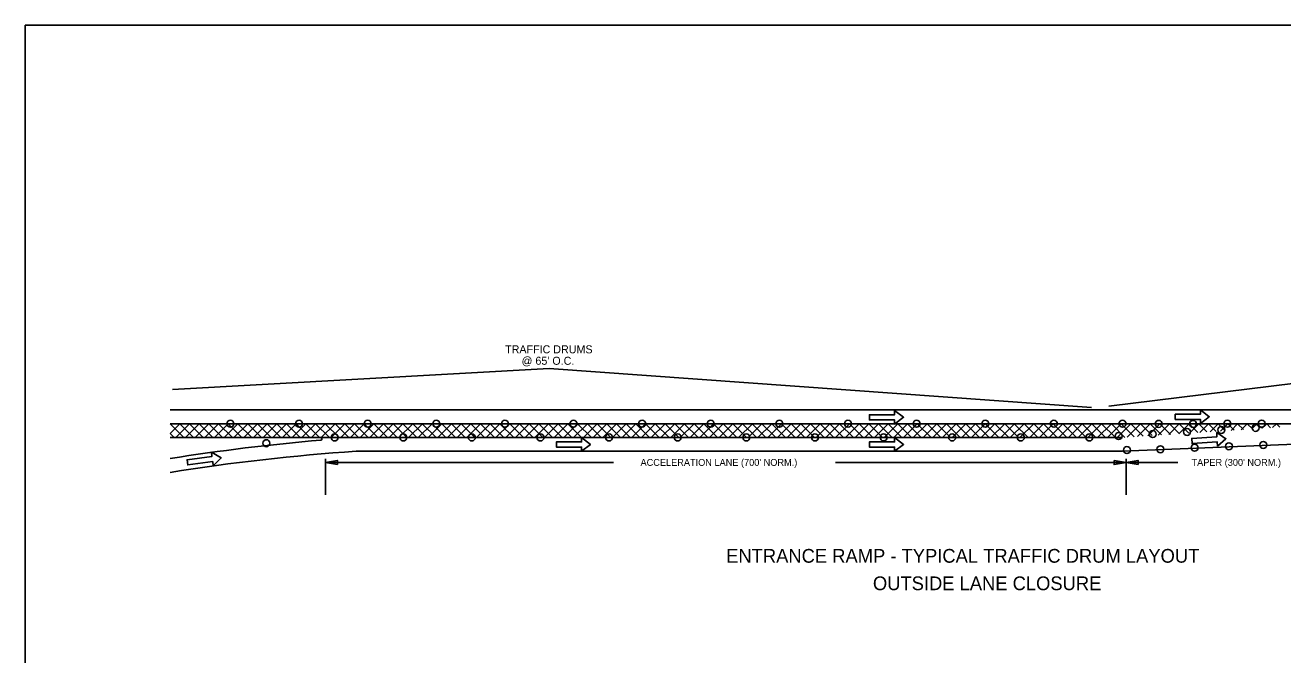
# Model space of a CAD drawing. Extents: x 1374027 to 1374537, y 380415 to 381405.
# Drawn here: x 1374367.1 to 1374477.1, y 380690.2 to 380745.2 of the extents above; entities that cross this region are included whole.
import ezdxf

# ---------------------------------------------------------------- set-up
doc = ezdxf.new("R2010")
doc.units = 0
for name, color, linetype in [('Default', 7, 'Continuous'), ('DSN_DRFT_Junk-No-Plot', 7, 'Continuous'), ('Edge of Lanes', 7, 'Continuous'), ('Level 1', 7, 'Continuous'), ('Level 40', 7, 'Continuous'), ('NOTES', 7, 'Continuous')]:
    doc.layers.add(name, color=color, linetype=linetype)

msp = doc.modelspace()

# ---------------------------------------------------------------- linework, layer by layer
at = {"layer": 'Default'}
for points in [[(1374469.84, 380710.37), (1374470.62, 380710.97), (1374469.84, 380711.57), (1374469.84, 380711.19), (1374467.64, 380711.19), (1374467.64, 380710.74), (1374469.84, 380710.74)], [(1374443.11, 380710.32), (1374443.89, 380710.92), (1374443.11, 380711.52), (1374443.11, 380711.15), (1374440.9, 380711.15), (1374440.9, 380710.7), (1374443.11, 380710.7)], [(1374471.35, 380708.4), (1374472.08, 380709.05), (1374471.27, 380709.59), (1374471.29, 380709.22), (1374469.09, 380709.07), (1374469.12, 380708.62), (1374471.32, 380708.77)], [(1374415.73, 380707.95), (1374416.51, 380708.55), (1374415.73, 380709.15), (1374415.73, 380708.77), (1374413.53, 380708.77), (1374413.53, 380708.32), (1374415.73, 380708.32)], [(1374443.11, 380707.95), (1374443.89, 380708.55), (1374443.11, 380709.15), (1374443.11, 380708.77), (1374440.9, 380708.77), (1374440.9, 380708.32), (1374443.11, 380708.32)], [(1374383.53, 380706.68), (1374384.23, 380707.38), (1374383.38, 380707.87), (1374383.42, 380707.5), (1374381.24, 380707.21), (1374381.3, 380706.76), (1374383.48, 380707.05)]]:
    msp.add_lwpolyline(points, close=True, dxfattribs=at)
at = {"layer": 'DSN_DRFT_Junk-No-Plot'}
for points in [[(1374367.08, 380745.17), (1374537.08, 380745.17), (1374537.08, 380635.17), (1374367.08, 380635.17)], [(1374367.08, 380745.17), (1374367.08, 380635.17), (1374537.08, 380635.17), (1374537.08, 380745.17)]]:
    msp.add_lwpolyline(points, close=True, dxfattribs=at)
at = {"layer": 'Edge of Lanes'}
for p, q in [((1374519.71, 380711.56), (1374379.75, 380711.56)), ((1374519.71, 380710.36), (1374379.75, 380710.36)), ((1374379.75, 380709.51), (1374380.6, 380710.36)), ((1374379.75, 380710.36), (1374379.75, 380710.36)), ((1374379.75, 380710.36), (1374380.95, 380709.16)), ((1374379.75, 380709.51), (1374380.1, 380709.16)), ((1374380.25, 380709.16), (1374381.45, 380710.36)), ((1374380.6, 380710.36), (1374381.8, 380709.16)), ((1374381.1, 380709.16), (1374382.3, 380710.36)), ((1374381.45, 380710.36), (1374382.65, 380709.16)), ((1374381.95, 380709.16), (1374383.15, 380710.36)), ((1374382.3, 380710.36), (1374383.5, 380709.16)), ((1374382.8, 380709.16), (1374384, 380710.36)), ((1374383.15, 380710.36), (1374384.35, 380709.16)), ((1374383.64, 380709.16), (1374384.84, 380710.36)), ((1374384, 380710.36), (1374385.2, 380709.16)), ((1374384.49, 380709.16), (1374385.69, 380710.36)), ((1374384.84, 380710.36), (1374386.04, 380709.16)), ((1374385.34, 380709.16), (1374386.54, 380710.36)), ((1374385.69, 380710.36), (1374386.89, 380709.16)), ((1374386.19, 380709.16), (1374387.39, 380710.36)), ((1374386.54, 380710.36), (1374387.74, 380709.16)), ((1374387.04, 380709.16), (1374388.24, 380710.36)), ((1374387.39, 380710.36), (1374388.59, 380709.16)), ((1374387.89, 380709.16), (1374389.09, 380710.36)), ((1374388.24, 380710.36), (1374389.44, 380709.16)), ((1374388.74, 380709.16), (1374389.94, 380710.36)), ((1374389.09, 380710.36), (1374390.29, 380709.16)), ((1374389.58, 380709.16), (1374390.78, 380710.36)), ((1374389.94, 380710.36), (1374391.14, 380709.16)), ((1374390.43, 380709.16), (1374391.63, 380710.36)), ((1374390.78, 380710.36), (1374391.98, 380709.16)), ((1374391.28, 380709.16), (1374392.48, 380710.36)), ((1374391.63, 380710.36), (1374392.83, 380709.16)), ((1374392.13, 380709.16), (1374393.33, 380710.36)), ((1374392.48, 380710.36), (1374393.68, 380709.16)), ((1374392.98, 380709.16), (1374394.18, 380710.36)), ((1374393.33, 380710.36), (1374394.53, 380709.16)), ((1374393.83, 380709.16), (1374395.03, 380710.36)), ((1374394.18, 380710.36), (1374395.38, 380709.16)), ((1374394.68, 380709.16), (1374395.88, 380710.36)), ((1374395.03, 380710.36), (1374396.23, 380709.16)), ((1374395.52, 380709.16), (1374396.72, 380710.36)), ((1374395.87, 380710.36), (1374397.08, 380709.16)), ((1374396.37, 380709.16), (1374397.57, 380710.36)), ((1374396.72, 380710.36), (1374397.92, 380709.16)), ((1374397.22, 380709.16), (1374398.42, 380710.36)), ((1374397.57, 380710.36), (1374398.77, 380709.16)), ((1374398.07, 380709.16), (1374399.27, 380710.36)), ((1374398.42, 380710.36), (1374399.62, 380709.16)), ((1374398.92, 380709.16), (1374400.12, 380710.36)), ((1374399.27, 380710.36), (1374400.47, 380709.16)), ((1374399.77, 380709.16), (1374400.97, 380710.36)), ((1374400.12, 380710.36), (1374401.32, 380709.16)), ((1374400.61, 380709.16), (1374401.82, 380710.36)), ((1374400.97, 380710.36), (1374402.17, 380709.16)), ((1374401.46, 380709.16), (1374402.66, 380710.36)), ((1374401.81, 380710.36), (1374403.01, 380709.16)), ((1374402.31, 380709.16), (1374403.51, 380710.36)), ((1374402.66, 380710.36), (1374403.86, 380709.16)), ((1374403.16, 380709.16), (1374404.36, 380710.36)), ((1374403.51, 380710.36), (1374404.71, 380709.16)), ((1374404.01, 380709.16), (1374405.21, 380710.36)), ((1374404.36, 380710.36), (1374405.56, 380709.16)), ((1374404.86, 380709.16), (1374406.06, 380710.36)), ((1374405.21, 380710.36), (1374406.41, 380709.16)), ((1374405.71, 380709.16), (1374406.91, 380710.36)), ((1374406.06, 380710.36), (1374407.26, 380709.16)), ((1374406.55, 380709.16), (1374407.75, 380710.36)), ((1374406.91, 380710.36), (1374408.11, 380709.16)), ((1374407.4, 380709.16), (1374408.6, 380710.36)), ((1374407.75, 380710.36), (1374408.95, 380709.16)), ((1374408.25, 380709.16), (1374409.45, 380710.36)), ((1374408.6, 380710.36), (1374409.8, 380709.16)), ((1374409.1, 380709.16), (1374410.3, 380710.36)), ((1374409.45, 380710.36), (1374410.65, 380709.16)), ((1374409.95, 380709.16), (1374411.15, 380710.36)), ((1374410.3, 380710.36), (1374411.5, 380709.16)), ((1374410.8, 380709.16), (1374412, 380710.36)), ((1374411.15, 380710.36), (1374412.35, 380709.16)), ((1374411.65, 380709.16), (1374412.85, 380710.36)), ((1374412, 380710.36), (1374413.2, 380709.16)), ((1374412.49, 380709.16), (1374413.69, 380710.36)), ((1374412.85, 380710.36), (1374414.05, 380709.16)), ((1374413.34, 380709.16), (1374414.54, 380710.36)), ((1374413.69, 380710.36), (1374414.89, 380709.16)), ((1374414.19, 380709.16), (1374415.39, 380710.36)), ((1374414.54, 380710.36), (1374415.74, 380709.16)), ((1374415.04, 380709.16), (1374416.24, 380710.36)), ((1374415.39, 380710.36), (1374416.59, 380709.16)), ((1374415.89, 380709.16), (1374417.09, 380710.36)), ((1374416.24, 380710.36), (1374417.44, 380709.16)), ((1374416.74, 380709.16), (1374417.94, 380710.36)), ((1374417.09, 380710.36), (1374418.29, 380709.16)), ((1374417.59, 380709.16), (1374418.79, 380710.36)), ((1374417.94, 380710.36), (1374419.14, 380709.16)), ((1374418.43, 380709.16), (1374419.63, 380710.36)), ((1374418.79, 380710.36), (1374419.99, 380709.16)), ((1374419.28, 380709.16), (1374420.48, 380710.36)), ((1374419.63, 380710.36), (1374420.83, 380709.16)), ((1374420.13, 380709.16), (1374421.33, 380710.36)), ((1374420.48, 380710.36), (1374421.68, 380709.16)), ((1374420.98, 380709.16), (1374422.18, 380710.36)), ((1374421.33, 380710.36), (1374422.53, 380709.16)), ((1374421.83, 380709.16), (1374423.03, 380710.36)), ((1374422.18, 380710.36), (1374423.38, 380709.16)), ((1374422.68, 380709.16), (1374423.88, 380710.36)), ((1374423.03, 380710.36), (1374424.23, 380709.16)), ((1374423.53, 380709.16), (1374424.73, 380710.36)), ((1374423.88, 380710.36), (1374425.08, 380709.16)), ((1374424.37, 380709.16), (1374425.57, 380710.36)), ((1374424.72, 380710.36), (1374425.93, 380709.16)), ((1374425.22, 380709.16), (1374426.42, 380710.36)), ((1374425.57, 380710.36), (1374426.77, 380709.16)), ((1374426.07, 380709.16), (1374427.27, 380710.36)), ((1374426.42, 380710.36), (1374427.62, 380709.16)), ((1374426.92, 380709.16), (1374428.12, 380710.36)), ((1374427.27, 380710.36), (1374428.47, 380709.16)), ((1374427.77, 380709.16), (1374428.97, 380710.36)), ((1374428.12, 380710.36), (1374429.32, 380709.16)), ((1374428.62, 380709.16), (1374429.82, 380710.36)), ((1374428.97, 380710.36), (1374430.17, 380709.16)), ((1374429.46, 380709.16), (1374430.67, 380710.36)), ((1374429.82, 380710.36), (1374431.02, 380709.16)), ((1374430.31, 380709.16), (1374431.51, 380710.36)), ((1374430.66, 380710.36), (1374431.86, 380709.16)), ((1374431.16, 380709.16), (1374432.36, 380710.36)), ((1374431.51, 380710.36), (1374432.71, 380709.16)), ((1374432.01, 380709.16), (1374433.21, 380710.36)), ((1374432.36, 380710.36), (1374433.56, 380709.16)), ((1374432.86, 380709.16), (1374434.06, 380710.36)), ((1374433.21, 380710.36), (1374434.41, 380709.16)), ((1374433.71, 380709.16), (1374434.91, 380710.36)), ((1374434.06, 380710.36), (1374435.26, 380709.16)), ((1374434.56, 380709.16), (1374435.76, 380710.36)), ((1374434.91, 380710.36), (1374436.11, 380709.16)), ((1374435.4, 380709.16), (1374436.6, 380710.36)), ((1374435.76, 380710.36), (1374436.96, 380709.16)), ((1374436.25, 380709.16), (1374437.45, 380710.36)), ((1374436.6, 380710.36), (1374437.8, 380709.16)), ((1374437.1, 380709.16), (1374438.3, 380710.36)), ((1374437.45, 380710.36), (1374438.65, 380709.16)), ((1374437.95, 380709.16), (1374439.15, 380710.36)), ((1374438.3, 380710.36), (1374439.5, 380709.16)), ((1374438.8, 380709.16), (1374440, 380710.36)), ((1374439.15, 380710.36), (1374440.35, 380709.16)), ((1374439.65, 380709.16), (1374440.85, 380710.36)), ((1374440, 380710.36), (1374441.2, 380709.16)), ((1374440.5, 380709.16), (1374441.7, 380710.36)), ((1374440.85, 380710.36), (1374442.05, 380709.16)), ((1374441.34, 380709.16), (1374442.54, 380710.36)), ((1374441.7, 380710.36), (1374442.9, 380709.16)), ((1374442.19, 380709.16), (1374443.39, 380710.36)), ((1374442.54, 380710.36), (1374443.74, 380709.16)), ((1374443.04, 380709.16), (1374444.24, 380710.36)), ((1374443.39, 380710.36), (1374444.59, 380709.16)), ((1374443.89, 380709.16), (1374445.09, 380710.36)), ((1374444.24, 380710.36), (1374445.44, 380709.16)), ((1374444.74, 380709.16), (1374445.94, 380710.36)), ((1374445.09, 380710.36), (1374446.29, 380709.16)), ((1374445.59, 380709.16), (1374446.79, 380710.36)), ((1374445.94, 380710.36), (1374447.14, 380709.16)), ((1374446.44, 380709.16), (1374447.64, 380710.36)), ((1374446.79, 380710.36), (1374447.99, 380709.16)), ((1374447.28, 380709.16), (1374448.48, 380710.36)), ((1374447.64, 380710.36), (1374448.84, 380709.16)), ((1374448.13, 380709.16), (1374449.33, 380710.36)), ((1374448.48, 380710.36), (1374449.68, 380709.16)), ((1374448.98, 380709.16), (1374450.18, 380710.36)), ((1374449.33, 380710.36), (1374450.53, 380709.16)), ((1374449.83, 380709.16), (1374451.03, 380710.36)), ((1374450.18, 380710.36), (1374451.38, 380709.16)), ((1374450.68, 380709.16), (1374451.88, 380710.36)), ((1374451.03, 380710.36), (1374452.23, 380709.16)), ((1374451.53, 380709.16), (1374452.73, 380710.36)), ((1374451.88, 380710.36), (1374453.08, 380709.16)), ((1374452.38, 380709.16), (1374453.58, 380710.36)), ((1374452.73, 380710.36), (1374453.93, 380709.16)), ((1374453.22, 380709.16), (1374454.42, 380710.36)), ((1374453.57, 380710.36), (1374454.78, 380709.16)), ((1374454.07, 380709.16), (1374455.27, 380710.36)), ((1374454.42, 380710.36), (1374455.62, 380709.16)), ((1374454.92, 380709.16), (1374456.12, 380710.36)), ((1374455.27, 380710.36), (1374456.47, 380709.16)), ((1374455.77, 380709.16), (1374456.97, 380710.36)), ((1374456.12, 380710.36), (1374457.32, 380709.16)), ((1374456.62, 380709.16), (1374457.82, 380710.36)), ((1374456.97, 380710.36), (1374458.17, 380709.16)), ((1374457.47, 380709.16), (1374458.67, 380710.36)), ((1374457.82, 380710.36), (1374459.02, 380709.16)), ((1374458.31, 380709.16), (1374459.52, 380710.36)), ((1374458.67, 380710.36), (1374459.87, 380709.16)), ((1374459.16, 380709.16), (1374460.36, 380710.36)), ((1374459.51, 380710.36), (1374460.71, 380709.16)), ((1374460.01, 380709.16), (1374461.21, 380710.36)), ((1374460.36, 380710.36), (1374461.56, 380709.16)), ((1374460.86, 380709.16), (1374462.06, 380710.36)), ((1374461.21, 380710.36), (1374462.41, 380709.16)), ((1374461.71, 380709.16), (1374462.91, 380710.36)), ((1374462.06, 380710.36), (1374463.25, 380709.17)), ((1374462.56, 380709.16), (1374463.76, 380710.36)), ((1374462.91, 380710.36), (1374464.04, 380709.22)), ((1374463.43, 380709.18), (1374464.61, 380710.36)), ((1374463.76, 380710.36), (1374464.84, 380709.27)), ((1374464.34, 380709.24), (1374465.45, 380710.36)), ((1374464.61, 380710.36), (1374465.63, 380709.33)), ((1374465.25, 380709.3), (1374466.3, 380710.36)), ((1374465.45, 380710.36), (1374466.43, 380709.38)), ((1374466.16, 380709.36), (1374467.15, 380710.36)), ((1374466.3, 380710.36), (1374467.23, 380709.43)), ((1374467.07, 380709.42), (1374468, 380710.36)), ((1374467.15, 380710.36), (1374468.02, 380709.48)), ((1374467.97, 380709.48), (1374468.85, 380710.36)), ((1374468, 380710.36), (1374468.82, 380709.54)), ((1374468.85, 380710.36), (1374469.61, 380709.59)), ((1374468.88, 380709.54), (1374469.7, 380710.36)), ((1374469.7, 380710.36), (1374470.41, 380709.64)), ((1374469.79, 380709.6), (1374470.55, 380710.36)), ((1374470.55, 380710.36), (1374471.21, 380709.69)), ((1374470.7, 380709.66), (1374471.39, 380710.36)), ((1374471.39, 380710.36), (1374472, 380709.75)), ((1374471.61, 380709.72), (1374472.24, 380710.36)), ((1374472.24, 380710.36), (1374472.8, 380709.8)), ((1374472.52, 380709.78), (1374473.09, 380710.36)), ((1374473.09, 380710.36), (1374473.6, 380709.85)), ((1374473.42, 380709.84), (1374473.94, 380710.36)), ((1374473.94, 380710.36), (1374474.39, 380709.9)), ((1374474.33, 380709.9), (1374474.79, 380710.36)), ((1374474.79, 380710.36), (1374475.19, 380709.96)), ((1374475.24, 380709.96), (1374475.64, 380710.36)), ((1374475.64, 380710.36), (1374475.98, 380710.01)), ((1374476.15, 380710.02), (1374476.49, 380710.36)), ((1374476.49, 380710.36), (1374476.78, 380710.06)), ((1374392.93, 380709.16), (1374379.75, 380709.16)), ((1374463.04, 380709.16), (1374392.93, 380709.16)), ((1374463.04, 380707.96), (1374493.04, 380709.16)), ((1374463.04, 380707.96), (1374396.02, 380707.96))]:
    msp.add_line(p, q, dxfattribs=at)
for centre, radius, start, end in [((1374408.06, 380529.5), 180.06, 94.8177, 99.0452), ((1374392.92, 380709.04), 0.116, 278.872, 86.6139), ((1374408.06, 380529.5), 178.86, 93.859, 99.1064)]:
    msp.add_arc(centre, radius, start, end, dxfattribs=at)
at = {"layer": 'Level 1'}
for points in [[(1374460.32, 380711.77), (1374412.91, 380715.19), (1374379.97, 380713.36)], [(1374517.55, 380711.75), (1374486.2, 380714.89), (1374461.85, 380711.9)]]:
    msp.add_lwpolyline(points, dxfattribs=at)
at = {"layer": 'Level 40'}
for centre in [(1374385.03, 380710.36), (1374385.03, 380710.36), (1374391.03, 380710.36), (1374391.03, 380710.36), (1374397.03, 380710.36), (1374403.03, 380710.36), (1374409.03, 380710.36), (1374415.03, 380710.36), (1374421.03, 380710.36), (1374427.03, 380710.36), (1374433.03, 380710.36), (1374439.03, 380710.36), (1374445.03, 380710.36), (1374451.03, 380710.36), (1374457.03, 380710.36), (1374463.03, 380710.36), (1374463.03, 380710.36), (1374466.2, 380710.35), (1374469.2, 380710.35), (1374472.2, 380710.36), (1374475.2, 380710.37), (1374394.14, 380709.16), (1374400.14, 380709.16), (1374406.14, 380709.16), (1374412.14, 380709.16), (1374418.14, 380709.16), (1374424.14, 380709.16), (1374430.14, 380709.16), (1374436.14, 380709.16), (1374442.14, 380709.16), (1374448.14, 380709.16), (1374454.14, 380709.16), (1374460.14, 380709.16), (1374462.69, 380709.28), (1374465.68, 380709.46), (1374468.68, 380709.64), (1374471.67, 380709.82), (1374474.67, 380710), (1374388.18, 380708.66), (1374463.42, 380708.06), (1374466.35, 380708.13), (1374469.34, 380708.26), (1374472.34, 380708.39), (1374475.34, 380708.51)]:
    msp.add_circle(centre, 0.305, dxfattribs=at)
at = {"layer": 'NOTES'}
for p, q in [((1374393.34, 380704.15), (1374393.34, 380707.28)), ((1374463.34, 380704.15), (1374463.34, 380707.28)), ((1374463.34, 380704.15), (1374463.34, 380707.28)), ((1374418.53, 380706.98), (1374393.34, 380706.98)), ((1374463.34, 380706.98), (1374437.94, 380706.98)), ((1374467.86, 380706.98), (1374463.34, 380706.98))]:
    msp.add_line(p, q, dxfattribs=at)
for points in [[(1374394.39, 380706.79), (1374393.34, 380706.98), (1374394.39, 380707.16)], [(1374462.29, 380707.16), (1374463.34, 380706.98), (1374462.29, 380706.79)], [(1374464.39, 380706.79), (1374463.34, 380706.98), (1374464.39, 380707.16)]]:
    msp.add_lwpolyline(points, close=True, dxfattribs=at)

# ---------------------------------------------------------------- texts
at = {"layer": 'Level 1'}
for s, height, p in [('TRAFFIC DRUMS ', 0.7, (1374409.05, 380716.51)), ("@ 65' O.C.", 0.7, (1374410.49, 380715.51)), ('ENTRANCE RAMP - TYPICAL TRAFFIC DRUM LAYOUT', 1.2, (1374428.38, 380698.22)), ('OUTSIDE LANE CLOSURE', 1.2, (1374441.21, 380695.82))]:
    msp.add_text(s, height=height, rotation=360, dxfattribs=at).set_placement(p)
at = {"layer": 'NOTES'}
for s, p in [("ACCELERATION LANE (700' NORM.)", (1374420.89, 380706.68)), ("TAPER (300' NORM.)", (1374469.07, 380706.68))]:
    msp.add_text(s, height=0.6, dxfattribs=at).set_placement(p)

doc.saveas('drawing.dxf')
